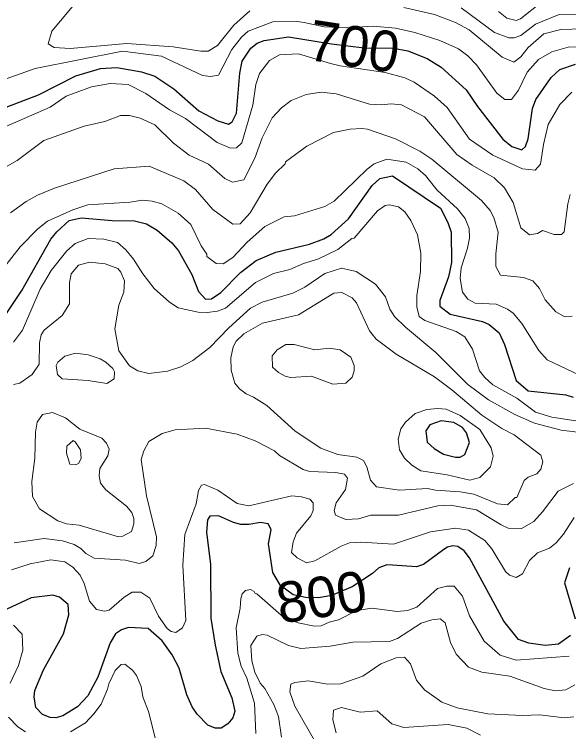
# Model space of a CAD drawing. Extents: x 673.3 to 698.5, y 6984.3 to 7012.3.
# Drawn here: x 679.596 to 680.69, y 6992.938 to 6994.352 of the extents above; entities that cross this region are included whole.
import ezdxf
from ezdxf.enums import TextEntityAlignment as Align

# ---------------------------------------------------------------- set-up
doc = ezdxf.new("R2010")
doc.units = 0
doc.header["$LTSCALE"] = 0.032
doc.layers.add('1', color=7, linetype='Continuous', lineweight=25)
doc.layers.add('2', color=7, linetype='Continuous', lineweight=13)
doc.layers.add('61', color=7, linetype='Continuous')

msp = doc.modelspace()

# ---------------------------------------------------------------- linework, layer by layer
at = {"layer": '1'}
for points in [[(680.0459, 6994.2603), (680.0629, 6994.286), (680.0755, 6994.2956), (680.089, 6994.3011), (680.137, 6994.3082), (680.2223, 6994.2944), (680.2863, 6994.2864), (680.3443, 6994.286), (680.3727, 6994.2807), (680.4108, 6994.2653), (680.4385, 6994.2481), (680.4877, 6994.2037), (680.5099, 6994.1707), (680.5602, 6994.106), (680.5779, 6994.0916), (680.598, 6994.0852), (680.6048, 6994.0918), (680.6104, 6994.1066), (680.6186, 6994.1668), (680.6252, 6994.1848), (680.6558, 6994.2282), (680.6724, 6994.2438), (680.7035, 6994.2539)], [(679.5799, 6994.1696), (679.644, 6994.1936), (679.7173, 6994.2309), (679.7662, 6994.2456), (679.7988, 6994.2479), (679.847, 6994.2391), (679.8734, 6994.2308), (679.9107, 6994.2058), (679.9604, 6994.162), (679.9977, 6994.1427), (680.0189, 6994.1356), (680.0264, 6994.1405), (680.0347, 6994.1574), (680.0411, 6994.2362), (680.0459, 6994.2603)], [(679.5808, 6993.7623), (679.6113, 6993.8076), (679.6681, 6993.9089), (679.6802, 6993.9236), (679.7043, 6993.9459), (679.7278, 6993.9514), (679.789, 6993.9458), (679.8334, 6993.9449), (679.8571, 6993.9393), (679.8783, 6993.927), (679.9071, 6993.9016), (679.92, 6993.8861), (679.9466, 6993.8394), (679.9597, 6993.8055), (679.9736, 6993.7907), (679.9855, 6993.7911), (680.004, 6993.8035), (680.0426, 6993.843), (680.0737, 6993.8667), (680.1125, 6993.8833), (680.1787, 6993.8989), (680.207, 6993.9099), (680.2214, 6993.9183), (680.2557, 6993.9493), (680.3023, 6994.0148), (680.3173, 6994.0287), (680.3422, 6994.0337), (680.4369, 6993.9702), (680.4515, 6993.942), (680.4581, 6993.9227), (680.4589, 6993.8632), (680.4533, 6993.8345), (680.4357, 6993.7882), (680.4356, 6993.7771), (680.4561, 6993.7609), (680.5204, 6993.7463), (680.5333, 6993.7404), (680.5532, 6993.7244), (680.5638, 6993.7014), (680.5865, 6993.6304), (680.6103, 6993.6096), (680.6845, 6993.6021), (680.6992, 6993.5972)], [(680.6935, 6993.1273), (680.6701, 6993.1104), (680.6438, 6993.1078), (680.6115, 6993.1119), (680.5911, 6993.1192), (680.5622, 6993.1553), (680.4941, 6993.2802), (680.4838, 6993.2944), (680.4712, 6993.3028), (680.4613, 6993.3043), (680.4512, 6993.3016), (680.4438, 6993.2969), (680.4038, 6993.2672), (680.3897, 6993.2626), (680.3428, 6993.2658), (680.3316, 6993.2667), (680.3156, 6993.261), (680.3028, 6993.2493), (680.2627, 6993.223), (680.222, 6993.2064), (680.1968, 6993.2014), (680.1706, 6993.2023), (680.1463, 6993.2076), (680.1213, 6993.2257), (680.1063, 6993.2514), (680.0981, 6993.308), (680.1029, 6993.3366), (680.0969, 6993.3477), (680.0818, 6993.3504), (680.0587, 6993.3459), (680.0431, 6993.3464), (680.029, 6993.3501), (679.9989, 6993.3634), (679.9823, 6993.3628), (679.9775, 6993.3551), (679.9752, 6993.3309), (679.9833, 6993.267), (679.9842, 6993.1612), (679.9923, 6993.1081), (680.0037, 6993.056), (680.0255, 6993.0042), (680.0314, 6992.9779), (680.0273, 6992.9645), (680.0177, 6992.9533), (680.0047, 6992.9443), (679.9927, 6992.9442), (679.9779, 6992.9506), (679.9569, 6992.9721), (679.9469, 6992.9867), (679.9368, 6993.0104), (679.9213, 6993.0625), (679.9078, 6993.0893), (679.8882, 6993.1165), (679.8606, 6993.141), (679.8213, 6993.1428), (679.8076, 6993.1384), (679.7961, 6993.1305), (679.7852, 6993.1129), (679.7608, 6993.0453), (679.741, 6993.0079), (679.7206, 6992.9866), (679.692, 6992.969), (679.678, 6992.9645), (679.6669, 6992.9655), (679.652, 6992.9711), (679.6386, 6992.985), (679.6357, 6993.0061), (679.6369, 6993.0185), (679.6537, 6993.0592), (679.6931, 6993.1302), (679.704, 6993.1678), (679.7022, 6993.1885), (679.6856, 6993.2028), (679.6719, 6993.2071), (679.6294, 6993.2015), (679.5815, 6993.179)], [(680.6919, 6993.2609), (680.6821, 6993.231), (680.7032, 6993.16)]]:
    msp.add_lwpolyline(points, dxfattribs=at)
msp.add_lwpolyline([(680.4666, 6993.4792), (680.4763, 6993.4793), (680.4853, 6993.4845), (680.4947, 6993.5082), (680.4882, 6993.5267), (680.4809, 6993.5378), (680.4635, 6993.5475), (680.4386, 6993.5506), (680.416, 6993.5428), (680.4085, 6993.5309), (680.4112, 6993.5083), (680.4246, 6993.4958), (680.4429, 6993.4852)], close=True, dxfattribs=at)
at = {"layer": '2'}
for points in [[(680.0609, 6994.3594), (680.0293, 6994.3313), (679.9972, 6994.2912), (679.979, 6994.2796), (679.964, 6994.2795), (679.9095, 6994.2886), (679.818, 6994.2951), (679.7065, 6994.2853), (679.675, 6994.287), (679.6627, 6994.2942), (679.6705, 6994.319), (679.7248, 6994.3852)], [(680.5514, 6994.3583), (680.5683, 6994.3452), (680.5868, 6994.34), (680.5952, 6994.3434), (680.6365, 6994.3766)], [(680.7187, 6994.3236), (680.6744, 6994.3228), (680.6412, 6994.3137), (680.6099, 6994.2872), (680.5954, 6994.2689), (680.5822, 6994.258), (680.5591, 6994.2683), (680.494, 6994.322), (680.4666, 6994.3365), (680.4251, 6994.352), (680.365, 6994.3661)], [(680.4783, 6994.3656), (680.5435, 6994.3169), (680.5718, 6994.3058), (680.5825, 6994.3059), (680.596, 6994.3108), (680.6246, 6994.3331), (680.6715, 6994.3521), (680.7242, 6994.3513)], [(680.7275, 6994.2886), (680.6891, 6994.2878), (680.6568, 6994.2788), (680.6306, 6994.2632), (680.6079, 6994.2382), (680.591, 6994.2026), (680.5775, 6994.1842), (680.5644, 6994.1848), (680.5484, 6994.1968), (680.508, 6994.2526), (680.491, 6994.2705), (680.4728, 6994.2845), (680.436, 6994.3006), (680.3863, 6994.3167), (680.3483, 6994.3253), (680.3045, 6994.3294), (680.2526, 6994.3261), (680.2075, 6994.328), (680.1683, 6994.3367), (680.1542, 6994.3382), (680.1063, 6994.3375), (680.0579, 6994.3196), (680.0448, 6994.3076), (680.0254, 6994.283), (679.999, 6994.2323), (679.9836, 6994.2301), (679.9676, 6994.2318), (679.8864, 6994.2699), (679.8097, 6994.2796), (679.6372, 6994.2454), (679.5802, 6994.2251)], [(679.5532, 6994.1203), (679.6668, 6994.1691), (679.6982, 6994.1912), (679.7484, 6994.2093), (679.7856, 6994.2163), (679.8208, 6994.2143), (679.8555, 6994.1966), (679.9024, 6994.1643), (679.9338, 6994.1469), (679.9962, 6994.0998), (680.0227, 6994.0884), (680.0349, 6994.0892), (680.0452, 6994.0992), (680.0669, 6994.1734), (680.0727, 6994.2143), (680.0799, 6994.2359), (680.0996, 6994.2616), (680.1196, 6994.2723), (680.1568, 6994.2748), (680.2203, 6994.2557), (680.2393, 6994.251), (680.3277, 6994.2378), (680.367, 6994.227), (680.3851, 6994.2185), (680.4253, 6994.1911), (680.4501, 6994.1687), (680.4941, 6994.1063), (680.5406, 6994.0747), (680.5988, 6994.0479), (680.6242, 6994.0453), (680.6348, 6994.0569), (680.6402, 6994.096), (680.6494, 6994.1349), (680.6726, 6994.1749), (680.6963, 6994.1989)], [(680.6932, 6993.997), (680.6885, 6993.9789), (680.681, 6993.9232), (680.6758, 6993.9185), (680.6612, 6993.9181), (680.6388, 6993.9261), (680.6288, 6993.9202), (680.6128, 6993.9175), (680.5959, 6993.9313), (680.5803, 6993.981), (680.5637, 6994.0104), (680.5431, 6994.0303), (680.4995, 6994.0547), (680.4695, 6994.0763), (680.4054, 6994.15), (680.3604, 6994.1738), (680.3396, 6994.1762), (680.3208, 6994.1739), (680.2968, 6994.1751), (680.2312, 6994.1956), (680.2015, 6994.199), (680.1718, 6994.1942), (680.1428, 6994.1822), (680.1232, 6994.1679), (680.1047, 6994.1484), (680.085, 6994.1092), (680.0711, 6994.0686), (680.0493, 6994.0258), (680.0268, 6994.0216), (680.0118, 6994.0289), (679.9794, 6994.0567), (679.9415, 6994.0746), (679.9103, 6994.0986), (679.8734, 6994.1347), (679.8448, 6994.1475), (679.8238, 6994.1527), (679.8057, 6994.1527), (679.7747, 6994.1414), (679.7343, 6994.132), (679.6545, 6994.1034), (679.6017, 6994.064), (679.5328, 6994.0254)], [(680.6973, 6993.757), (680.6814, 6993.7565), (680.6649, 6993.7654), (680.644, 6993.7896), (680.6324, 6993.8114), (680.6194, 6993.8269), (680.6012, 6993.8335), (680.5553, 6993.8382), (680.5461, 6993.8552), (680.5462, 6993.8803), (680.5509, 6993.923), (680.5423, 6993.9516), (680.5353, 6993.9655), (680.5183, 6993.985), (680.4204, 6994.0665), (680.3965, 6994.0825), (680.3485, 6994.1066), (680.2934, 6994.1258), (680.282, 6994.1274), (680.2592, 6994.1257), (680.2262, 6994.1191), (680.1737, 6994.0927), (680.1314, 6994.0618), (680.1305, 6994.0579), (680.1116, 6994.0389), (680.0953, 6994.0172), (680.0615, 6993.9607), (680.0418, 6993.9391), (680.0273, 6993.9386), (679.9877, 6993.9675), (679.9538, 6994.0071), (679.9304, 6994.0239), (679.862, 6994.0532), (679.793, 6994.0475), (679.6757, 6994.0099), (679.6419, 6993.9961), (679.6199, 6993.9836), (679.5889, 6993.9609)], [(680.71, 6993.6414), (680.6474, 6993.6712), (680.6311, 6993.6895), (680.5975, 6993.7428), (680.5809, 6993.7628), (680.5695, 6993.7709), (680.5471, 6993.7809), (680.5057, 6993.783), (680.4914, 6993.7905), (680.4808, 6993.8046), (680.4761, 6993.8316), (680.4777, 6993.8524), (680.4908, 6993.8915), (680.4947, 6993.9108), (680.4939, 6993.9303), (680.486, 6993.9496), (680.4708, 6993.9689), (680.4308, 6994.0057), (680.4076, 6994.0346), (680.3927, 6994.0478), (680.3692, 6994.0612), (680.3312, 6994.0671), (680.3061, 6994.0574), (680.2922, 6994.0468), (680.2274, 6993.9839), (680.2092, 6993.9736), (680.149, 6993.9548), (680.1289, 6993.953), (680.0906, 6993.9339), (680.0555, 6993.903), (680.0276, 6993.8729), (680.0083, 6993.8603), (679.9944, 6993.861), (679.9763, 6993.8749), (679.9759, 6993.8797), (679.9646, 6993.896), (679.9442, 6993.9376), (679.9196, 6993.96), (679.8871, 6993.9787), (679.8683, 6993.9841), (679.8488, 6993.9857), (679.8251, 6993.982), (679.7415, 6993.9767), (679.7115, 6993.9667), (679.662, 6993.9443), (679.6425, 6993.9291), (679.6076, 6993.8941), (679.575, 6993.8516)], [(680.7128, 6993.5492), (680.6566, 6993.5578), (680.6249, 6993.568), (680.5876, 6993.5953), (680.5403, 6993.6217), (680.5245, 6993.6359), (680.5143, 6993.6496), (680.5005, 6993.6923), (680.485, 6993.7161), (680.4679, 6993.7271), (680.4063, 6993.7488), (680.3949, 6993.7567), (680.3906, 6993.7754), (680.3905, 6993.798), (680.398, 6993.8454), (680.3987, 6993.8811), (680.3921, 6993.9173), (680.3786, 6993.9461), (680.3671, 6993.9627), (680.3541, 6993.9725), (680.3361, 6993.9767), (680.3278, 6993.9751), (680.3128, 6993.9649), (680.2671, 6993.9111), (680.2625, 6993.9104), (680.2348, 6993.8886), (680.1949, 6993.8694), (680.1666, 6993.861), (680.1396, 6993.8494), (680.1079, 6993.8415), (680.0722, 6993.8236), (680.013, 6993.7728), (679.9972, 6993.767), (679.9766, 6993.7643), (679.9591, 6993.7651), (679.9196, 6993.7738), (679.9025, 6993.7847), (679.8722, 6993.8117), (679.8499, 6993.8405), (679.8312, 6993.8698), (679.8165, 6993.8878), (679.8001, 6993.9026), (679.773, 6993.9091), (679.7419, 6993.91), (679.7164, 6993.9003), (679.6996, 6993.8859), (679.6689, 6993.8472), (679.6472, 6993.8101), (679.6126, 6993.7292), (679.5944, 6993.7059)], [(680.7243, 6993.5263), (680.675, 6993.532), (680.6225, 6993.5458), (680.5838, 6993.5629), (680.5322, 6993.5923), (680.491, 6993.6222), (680.4278, 6993.6855), (680.368, 6993.7353), (680.3467, 6993.7567), (680.3374, 6993.771), (680.3286, 6993.795), (680.3089, 6993.8205), (680.2706, 6993.8453), (680.242, 6993.852), (680.209, 6993.8415), (680.1696, 6993.8145), (680.146, 6993.8027), (680.0854, 6993.7846), (680.0624, 6993.7732), (680.0193, 6993.7341), (679.9823, 6993.6955), (679.9486, 6993.6699), (679.9245, 6993.657), (679.8985, 6993.6487), (679.8614, 6993.6437), (679.8398, 6993.6491), (679.8235, 6993.6594), (679.8023, 6993.6886), (679.7945, 6993.7318), (679.8025, 6993.7786), (679.8121, 6993.8043), (679.8139, 6993.8268), (679.8066, 6993.844), (679.8007, 6993.8513), (679.7755, 6993.8603), (679.7446, 6993.8636), (679.7226, 6993.8576), (679.7081, 6993.8404), (679.7049, 6993.8231), (679.7048, 6993.7816), (679.6905, 6993.7581), (679.6553, 6993.7292), (679.6494, 6993.72), (679.6462, 6993.7042), (679.6453, 6993.6626), (679.6315, 6993.642), (679.6068, 6993.6252), (679.5947, 6993.6225)], [(679.5956, 6993.3098), (679.6549, 6993.3187), (679.6913, 6993.3138), (679.7141, 6993.3064), (679.7276, 6993.2991), (679.737, 6993.2888), (679.7541, 6993.2795), (679.8153, 6993.2756), (679.8427, 6993.2691), (679.8558, 6993.2733), (679.8698, 6993.2841), (679.8758, 6993.3047), (679.8766, 6993.3218), (679.8571, 6993.4029), (679.8466, 6993.4745), (679.852, 6993.4916), (679.8618, 6993.5098), (679.8881, 6993.5255), (679.9138, 6993.5329), (679.9734, 6993.5361), (680.0357, 6993.5241), (680.0715, 6993.5112), (680.1098, 6993.4915), (680.1192, 6993.4821), (680.1665, 6993.4546), (680.1794, 6993.4507), (680.2308, 6993.449), (680.248, 6993.4456)], [(680.248, 6993.4456), (680.2536, 6993.4376), (680.2497, 6993.4152), (680.2315, 6993.389), (680.2276, 6993.3737), (680.2297, 6993.3648), (680.2507, 6993.3562), (680.2757, 6993.3571), (680.2999, 6993.3643), (680.3545, 6993.3644), (680.4321, 6993.383), (680.4571, 6993.3846), (680.5084, 6993.375), (680.5568, 6993.3452), (680.5709, 6993.3392), (680.5971, 6993.3383), (680.6214, 6993.3524), (680.6385, 6993.3711), (680.6693, 6993.4117)], [(679.928, 6993.1422), (679.9344, 6993.1569), (679.9287, 6993.2662), (679.9329, 6993.3263), (679.955, 6993.3869), (679.9599, 6993.413), (679.9657, 6993.4237), (679.9717, 6993.425), (679.9975, 6993.4139), (680.0357, 6993.3879), (680.0589, 6993.3831), (680.1436, 6993.4026), (680.1631, 6993.401), (680.1793, 6993.3961), (680.186, 6993.389), (680.1859, 6993.3736), (680.181, 6993.3633), (680.1533, 6993.3288), (680.1463, 6993.3117), (680.1433, 6993.2907), (680.1543, 6993.2805), (680.1727, 6993.2707), (680.1892, 6993.2746), (680.241, 6993.3037), (680.2578, 6993.3097), (680.2802, 6993.3114), (680.3442, 6993.3074), (680.4177, 6993.3318), (680.4669, 6993.339), (680.4923, 6993.335), (680.5247, 6993.3148), (680.5387, 6993.2984), (680.5653, 6993.2532), (680.5736, 6993.2459), (680.5863, 6993.2413), (680.5989, 6993.2488), (680.6127, 6993.2754), (680.6286, 6993.2906), (680.6521, 6993.2993), (680.6656, 6993.3103), (680.68, 6993.3272), (680.7007, 6993.36)], [(680.6693, 6993.4117), (680.6996, 6993.427)], [(679.5906, 6993.2566), (679.6278, 6993.2683), (679.668, 6993.2763), (679.6959, 6993.2723), (679.7119, 6993.2619), (679.7259, 6993.2462), (679.7341, 6993.2299), (679.7445, 6993.1947), (679.7581, 6993.1784), (679.7739, 6993.1755), (679.7832, 6993.1775), (679.8127, 6993.203), (679.8289, 6993.2125), (679.8457, 6993.2128), (679.8637, 6993.201), (679.8806, 6993.1651), (679.8979, 6993.1411), (679.9057, 6993.1351), (679.915, 6993.1331), (679.928, 6993.1422)], [(680.073, 6992.9342), (680.0704, 6992.9938), (680.0548, 6993.0432), (680.0437, 6993.0665), (680.0371, 6993.0925), (680.0339, 6993.1426), (680.0419, 6993.1811), (680.0429, 6993.2005), (680.0461, 6993.2095), (680.0526, 6993.216), (680.0623, 6993.2177), (680.0695, 6993.2143), (680.0713, 6993.2098), (680.0747, 6993.2094), (680.1278, 6993.163), (680.1562, 6993.1519), (680.1887, 6993.1453), (680.2016, 6993.1461), (680.2175, 6993.1536), (680.2362, 6993.1581), (680.2724, 6993.1762), (680.3018, 6993.181), (680.3516, 6993.1746), (680.3721, 6993.1763), (680.3903, 6993.1834), (680.4312, 6993.2199), (680.4498, 6993.2242)], [(680.4498, 6993.2242), (680.4643, 6993.2242), (680.4809, 6993.2047), (680.4942, 6993.1659), (680.5234, 6993.1158), (680.5551, 6993.0883), (680.5866, 6993.0785), (680.691, 6993.0867)], [(680.1234, 6992.9265), (680.1177, 6992.9677), (680.1084, 6992.9911), (680.0904, 6993.0226), (680.0815, 6993.0335), (680.0707, 6993.0551), (680.065, 6993.0774), (680.0632, 6993.1078), (680.0748, 6993.1258), (680.0852, 6993.1289), (680.0954, 6993.128), (680.1372, 6993.1076), (680.1615, 6993.1013), (680.2193, 6993.1062), (680.2641, 6993.1143), (680.3364, 6993.1152), (680.3525, 6993.121), (680.3993, 6993.1516), (680.4201, 6993.1582), (680.4366, 6993.1599), (680.4467, 6993.1523), (680.4566, 6993.1137), (680.468, 6993.0907), (680.4927, 6993.065), (680.5189, 6993.0551), (680.574, 6993.0467), (680.6416, 6993.0224), (680.6635, 6993.0183), (680.6845, 6993.0199), (680.7026, 6993.0298)], [(679.5948, 6993.1476), (679.6118, 6993.1298), (679.6128, 6993.0986), (679.6042, 6993.0681), (679.5881, 6993.0335)], [(680.1936, 6992.9108), (680.15, 6992.988), (680.1399, 6993.016), (680.1421, 6993.0309), (680.1495, 6993.0347), (680.1763, 6993.0378), (680.2148, 6993.0313), (680.2405, 6993.0317), (680.2841, 6993.0469), (680.3197, 6993.0711), (680.3494, 6993.0834), (680.3663, 6993.0843), (680.3782, 6993.0711), (680.3899, 6993.0388), (680.4055, 6993.0203), (680.4395, 6992.9958), (680.4701, 6992.9844), (680.5307, 6992.9727), (680.5992, 6992.9694), (680.6331, 6992.9709), (680.681, 6992.9645), (680.7003, 6992.9668)], [(679.7071, 6992.9374), (679.7366, 6992.9547), (679.7534, 6992.9724), (679.7674, 6992.9919), (679.7804, 6993.0213), (679.7825, 6993.0318), (679.7955, 6993.0579), (679.8072, 6993.0701), (679.814, 6993.0709), (679.8292, 6993.0591), (679.8375, 6993.0484), (679.8465, 6993.0265), (679.8499, 6993.0062), (679.8612, 6992.9773), (679.8743, 6992.9252)], [(680.5158, 6992.9303), (680.4893, 6992.9442), (680.4525, 6992.9515), (680.3648, 6992.9456), (680.3412, 6992.9528), (680.3124, 6992.9784), (680.2784, 6992.9762), (680.242, 6992.9849), (680.2263, 6992.9799), (680.2245, 6992.9607), (680.2311, 6992.9349)], [(679.5845, 6992.966), (679.6033, 6992.9468), (679.6186, 6992.937)]]:
    msp.add_lwpolyline(points, dxfattribs=at)
for points in [[(680.6025, 6993.4329), (680.6102, 6993.4398), (680.6275, 6993.4458), (680.6354, 6993.4553), (680.639, 6993.47), (680.6355, 6993.4831), (680.5825, 6993.5233), (680.558, 6993.5358), (680.519, 6993.5618), (680.4595, 6993.6121), (680.4253, 6993.6373), (680.3496, 6993.6821), (680.31, 6993.712), (680.2973, 6993.7282), (680.2716, 6993.7837), (680.2626, 6993.7935), (680.2423, 6993.8039), (680.2266, 6993.8023), (680.1571, 6993.7595), (680.0858, 6993.7432), (680.0491, 6993.7224), (680.0339, 6993.7079), (680.0282, 6993.6963), (680.0233, 6993.6749), (680.024, 6993.6505), (680.0311, 6993.6248), (680.0403, 6993.6135), (680.0534, 6993.6038), (680.0682, 6993.5975), (680.0947, 6993.5811), (680.1505, 6993.5304), (680.2011, 6993.4969), (680.2345, 6993.4842), (680.2724, 6993.4791), (680.2852, 6993.4727), (680.292, 6993.4596), (680.2992, 6993.4339), (680.3111, 6993.4205), (680.3565, 6993.4141), (680.4115, 6993.4173), (680.427, 6993.4141), (680.4763, 6993.4107), (680.5032, 6993.4063), (680.5496, 6993.3871), (680.5693, 6993.3847), (680.5843, 6993.3991), (680.5877, 6993.3997)], [(680.225, 6993.6233), (680.1829, 6993.6387), (680.1413, 6993.6364), (680.131, 6993.6386), (680.1172, 6993.646), (680.1055, 6993.6568), (680.1047, 6993.6787), (680.115, 6993.6908), (680.1318, 6993.7015), (680.1485, 6993.7015), (680.1892, 6993.6909), (680.2177, 6993.6942), (680.239, 6993.6909), (680.26, 6993.6763), (680.2667, 6993.6599), (680.2666, 6993.6496), (680.2627, 6993.6366), (680.2507, 6993.6247)], [(679.7418, 6993.6299), (679.7789, 6993.6242), (679.7935, 6993.6334), (679.7937, 6993.6472), (679.7903, 6993.6542), (679.7771, 6993.6666), (679.7654, 6993.6732), (679.7418, 6993.6811), (679.7168, 6993.6844), (679.6957, 6993.6785), (679.6819, 6993.6662), (679.6788, 6993.6599), (679.6812, 6993.6421), (679.6904, 6993.6338)], [(679.769, 6993.5165), (679.7255, 6993.5344), (679.6975, 6993.5565), (679.6714, 6993.5671), (679.6521, 6993.5632), (679.6415, 6993.5479), (679.6381, 6993.5286), (679.6364, 6993.4769), (679.6308, 6993.4313), (679.6323, 6993.4012), (679.646, 6993.3768), (679.6823, 6993.3532), (679.6994, 6993.3472), (679.7241, 6993.3446), (679.8015, 6993.322), (679.8102, 6993.3229), (679.8272, 6993.3322), (679.8318, 6993.3472), (679.8321, 6993.3579), (679.8278, 6993.37), (679.8174, 6993.382), (679.7767, 6993.4147), (679.766, 6993.4279), (679.7635, 6993.4424), (679.7649, 6993.4563), (679.7805, 6993.4814), (679.7831, 6993.4947), (679.7784, 6993.5064)], [(680.5361, 6993.46), (680.5412, 6993.4808), (680.5369, 6993.4976), (680.5148, 6993.5333), (680.4763, 6993.5613), (680.4483, 6993.5736), (680.4315, 6993.5752), (680.4104, 6993.5727), (680.3872, 6993.5652), (680.3679, 6993.5477), (680.3589, 6993.5348), (680.3539, 6993.5143), (680.3566, 6993.4933), (680.3659, 6993.4768), (680.3807, 6993.4632), (680.3987, 6993.4519), (680.4506, 6993.444), (680.4954, 6993.4336), (680.5146, 6993.439)], [(679.7058, 6993.4654), (679.6992, 6993.4871), (679.7, 6993.5008), (679.7121, 6993.5116), (679.7164, 6993.5091), (679.7268, 6993.4937), (679.7284, 6993.4762), (679.723, 6993.4663), (679.7167, 6993.4637)]]:
    msp.add_lwpolyline(points, close=True, dxfattribs=at)

# ---------------------------------------------------------------- texts
at = {"layer": '61'}
for s, rotation, p in [('700', 351.469, (680.2609, 6994.2498)), ('800', 8.607, (680.2086, 6993.1638))]:
    msp.add_text(s, height=0.08, rotation=rotation, dxfattribs=at).set_placement(p, align=Align.CENTER)

doc.saveas('drawing.dxf')
